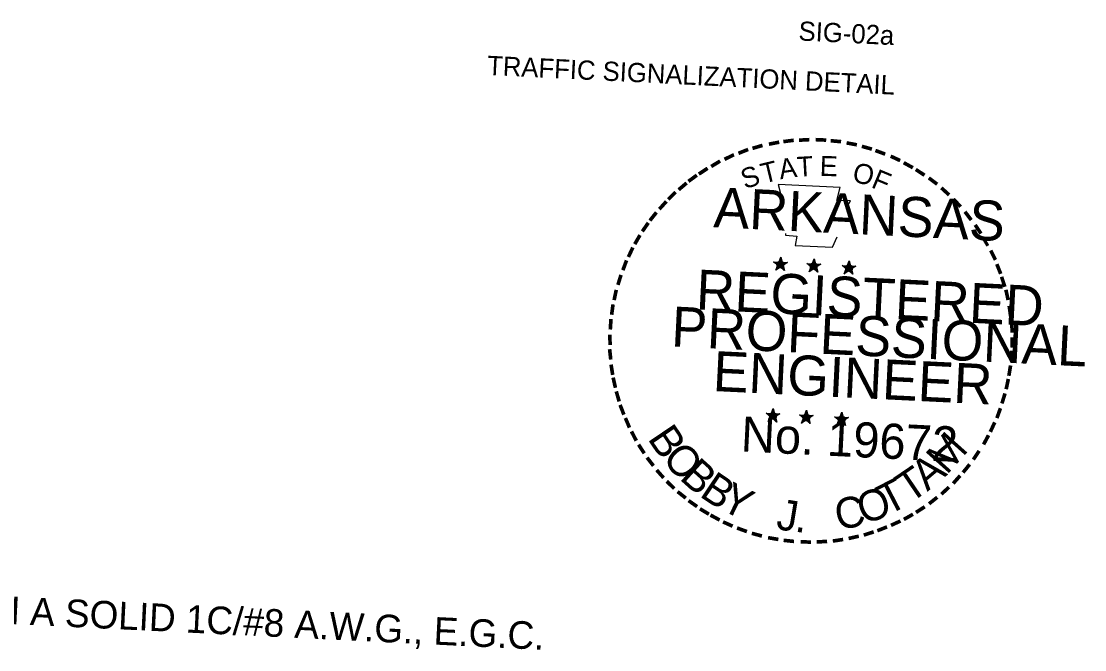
# Model space of a CAD drawing. Extents: x 661018 to 663325, y 642537 to 643074.
# Drawn here: x 662163.6 to 662293.4, y 642856.9 to 642933.6 of the extents above; entities that cross this region are included whole.
import ezdxf

# ---------------------------------------------------------------- set-up
doc = ezdxf.new("R2010")
doc.units = 0
doc.layers.add('R_Dimension', color=7, linetype='Continuous')
doc.layers.add('R_No Plot', color=7, linetype='Continuous')

msp = doc.modelspace()

# ---------------------------------------------------------------- linework, layer by layer
at = {"layer": 'R_No Plot'}
for p, q in [((662256.27, 642904.81), (662256.14, 642904.2)), ((662256.23, 642903.92), (662256.27, 642904.81)), ((662256.27, 642904.81), (662256.36, 642904.19)), ((662260.35, 642904.61), (662260.22, 642904)), ((662260.3, 642903.72), (662260.35, 642904.61)), ((662260.35, 642904.61), (662260.44, 642903.99)), ((662264.65, 642904.37), (662264.52, 642903.76)), ((662264.6, 642903.48), (662264.65, 642904.37)), ((662264.65, 642904.37), (662264.74, 642903.76)), ((662255.39, 642904.23), (662256.23, 642903.92)), ((662255.39, 642904.23), (662256, 642904.09)), ((662255.39, 642904.23), (662255.96, 642903.9)), ((662255.67, 642903.22), (662256.23, 642903.92)), ((662255.67, 642903.22), (662256.01, 642903.8)), ((662255.67, 642903.22), (662256.22, 642903.72)), ((662256.72, 642903.17), (662256.22, 642903.72)), ((662257.09, 642904.15), (662256.23, 642903.92)), ((662256.72, 642903.17), (662256.23, 642903.92)), ((662257.09, 642904.15), (662256.39, 642904.06)), ((662256.72, 642903.17), (662256.42, 642903.89)), ((662257.09, 642904.15), (662256.58, 642903.92)), ((662259.47, 642904.03), (662260.3, 642903.72)), ((662259.47, 642904.03), (662260.08, 642903.89)), ((662259.47, 642904.03), (662260.03, 642903.71)), ((662259.74, 642903.02), (662260.3, 642903.72)), ((662259.74, 642903.02), (662260.08, 642903.6)), ((662259.74, 642903.02), (662260.29, 642903.53)), ((662260.79, 642902.97), (662260.29, 642903.52)), ((662261.16, 642903.95), (662260.3, 642903.72)), ((662260.79, 642902.97), (662260.3, 642903.72)), ((662261.16, 642903.95), (662260.46, 642903.86)), ((662260.79, 642902.97), (662260.49, 642903.7)), ((662261.16, 642903.95), (662260.65, 642903.72)), ((662263.77, 642903.79), (662264.6, 642903.48)), ((662263.77, 642903.79), (662264.38, 642903.65)), ((662263.77, 642903.79), (662264.33, 642903.47)), ((662264.04, 642902.78), (662264.6, 642903.48)), ((662264.04, 642902.78), (662264.38, 642903.36)), ((662264.04, 642902.78), (662264.59, 642903.29)), ((662265.09, 642902.73), (662264.59, 642903.28)), ((662265.46, 642903.71), (662264.6, 642903.48)), ((662265.09, 642902.73), (662264.6, 642903.48)), ((662265.46, 642903.71), (662264.76, 642903.63)), ((662265.09, 642902.73), (662264.79, 642903.46)), ((662265.46, 642903.71), (662264.95, 642903.49)), ((662255.37, 642886.34), (662255.24, 642885.73)), ((662255.32, 642885.45), (662255.37, 642886.34)), ((662255.37, 642886.34), (662255.46, 642885.72)), ((662254.49, 642885.76), (662255.32, 642885.45)), ((662254.49, 642885.76), (662255.1, 642885.62)), ((662254.49, 642885.76), (662255.05, 642885.44)), ((662254.76, 642884.75), (662255.32, 642885.45)), ((662254.76, 642884.75), (662255.1, 642885.33)), ((662254.76, 642884.75), (662255.31, 642885.25)), ((662255.81, 642884.7), (662255.31, 642885.25)), ((662256.18, 642885.68), (662255.32, 642885.45)), ((662255.81, 642884.7), (662255.32, 642885.45)), ((662256.18, 642885.68), (662255.48, 642885.59)), ((662255.81, 642884.7), (662255.51, 642885.43)), ((662256.18, 642885.68), (662255.67, 642885.45)), ((662258.56, 642885.56), (662259.39, 642885.25)), ((662258.56, 642885.56), (662259.17, 642885.42)), ((662258.56, 642885.56), (662259.12, 642885.24)), ((662258.83, 642884.55), (662259.39, 642885.25)), ((662258.83, 642884.55), (662259.17, 642885.13)), ((662258.83, 642884.55), (662259.38, 642885.06)), ((662259.44, 642886.14), (662259.31, 642885.53)), ((662259.88, 642884.5), (662259.38, 642885.05)), ((662259.39, 642885.25), (662259.44, 642886.14)), ((662260.25, 642885.48), (662259.39, 642885.25)), ((662259.88, 642884.5), (662259.39, 642885.25)), ((662259.44, 642886.14), (662259.53, 642885.53)), ((662260.25, 642885.48), (662259.55, 642885.4)), ((662259.88, 642884.5), (662259.58, 642885.23)), ((662260.25, 642885.48), (662259.74, 642885.26)), ((662262.86, 642885.33), (662263.7, 642885.02)), ((662262.86, 642885.33), (662263.48, 642885.19)), ((662262.86, 642885.33), (662263.43, 642885)), ((662263.14, 642884.32), (662263.7, 642885.02)), ((662263.14, 642884.32), (662263.48, 642884.9)), ((662263.75, 642885.91), (662263.62, 642885.3)), ((662263.7, 642885.02), (662263.75, 642885.91)), ((662264.56, 642885.25), (662263.7, 642885.02)), ((662264.19, 642884.27), (662263.7, 642885.02)), ((662263.75, 642885.91), (662263.84, 642885.29)), ((662264.56, 642885.25), (662263.86, 642885.16)), ((662264.19, 642884.27), (662263.89, 642884.99)), ((662264.56, 642885.25), (662264.05, 642885.02)), ((662263.14, 642884.32), (662263.69, 642884.82)), ((662264.19, 642884.27), (662263.69, 642884.82))]:
    msp.add_line(p, q, dxfattribs=at)
for points in [[(662255.95, 642913.68), (662256.51, 642911.63)], [(662264.41, 642911.02), (662264.79, 642911.69), (662263.11, 642911.72), (662263.55, 642913.31), (662255.95, 642913.68)], [(662256.87, 642907.72), (662256.86, 642907.5), (662258.23, 642907.39), (662258.04, 642906.24), (662262.6, 642906.02), (662263.15, 642907.3)], [(662256.27, 642904.81), (662256.72, 642903.17), (662255.39, 642904.23), (662257.09, 642904.15), (662255.67, 642903.22), (662256.27, 642904.81)], [(662260.35, 642904.61), (662260.79, 642902.97), (662259.47, 642904.03), (662261.16, 642903.95), (662259.74, 642903.02), (662260.35, 642904.61)], [(662264.65, 642904.37), (662265.09, 642902.73), (662263.77, 642903.79), (662265.46, 642903.71), (662264.04, 642902.78), (662264.65, 642904.37)], [(662255.37, 642886.34), (662255.81, 642884.7), (662254.49, 642885.76), (662256.18, 642885.68), (662254.76, 642884.75), (662255.37, 642886.34)], [(662259.44, 642886.14), (662259.88, 642884.5), (662258.56, 642885.56), (662260.25, 642885.48), (662258.83, 642884.55), (662259.44, 642886.14)], [(662263.75, 642885.91), (662264.19, 642884.27), (662262.86, 642885.33), (662264.56, 642885.25), (662263.14, 642884.32), (662263.75, 642885.91)]]:
    msp.add_lwpolyline(points, dxfattribs=at)
for centre, radius in [((662256.23, 642903.92), 0.421), ((662256.23, 642903.92), 0.353), ((662256.23, 642903.92), 0.283), ((662256.23, 642903.92), 0.242), ((662256.23, 642903.92), 0.182), ((662256.23, 642903.92), 0.121), ((662256.23, 642903.92), 0.0724), ((662260.3, 642903.72), 0.421), ((662260.3, 642903.72), 0.353), ((662260.3, 642903.72), 0.283), ((662260.3, 642903.72), 0.242), ((662260.3, 642903.72), 0.182), ((662260.3, 642903.72), 0.121), ((662260.3, 642903.72), 0.0724), ((662264.6, 642903.48), 0.421), ((662264.6, 642903.48), 0.353), ((662264.6, 642903.48), 0.283), ((662264.6, 642903.48), 0.242), ((662264.6, 642903.48), 0.182), ((662264.6, 642903.48), 0.121), ((662264.6, 642903.48), 0.0724), ((662255.32, 642885.45), 0.421), ((662255.32, 642885.45), 0.353), ((662255.32, 642885.45), 0.283), ((662255.32, 642885.45), 0.242), ((662255.32, 642885.45), 0.182), ((662255.32, 642885.45), 0.121), ((662255.32, 642885.45), 0.0724), ((662259.39, 642885.25), 0.421), ((662259.39, 642885.25), 0.353), ((662259.39, 642885.25), 0.283), ((662259.39, 642885.25), 0.242), ((662259.39, 642885.25), 0.182), ((662259.39, 642885.25), 0.121), ((662259.39, 642885.25), 0.0724), ((662263.7, 642885.02), 0.421), ((662263.7, 642885.02), 0.353), ((662263.7, 642885.02), 0.283), ((662263.7, 642885.02), 0.242), ((662263.7, 642885.02), 0.182), ((662263.7, 642885.02), 0.121), ((662263.7, 642885.02), 0.0724)]:
    msp.add_circle(centre, radius, dxfattribs=at)

# ---------------------------------------------------------------- texts
at = {"layer": 'R_Dimension'}
msp.add_text(' 1/2" NMC WITH A SOLID 1C/#8 A.W.G., E.G.C.', height=3.3692, rotation=357.2199, dxfattribs=at).set_placement((662129.98, 642861.62))
at = {"layer": 'R_No Plot'}
for s, height, rotation, p in [('SIG-02a', 2.345, 357.2199, (662258.41, 642931.26)), ('TRAFFIC SIGNALIZATION DETAIL', 2.3448, 357.2199, (662220.39, 642927.06)), ('-', 3.91, 16.3944, (662253.03, 642916.58)), ('-', 3.91, 10.8485, (662254.89, 642917.08)), ('-', 3.91, 7.4377, (662256.56, 642917.39)), ('-', 3.91, 3.1152, (662258.35, 642917.57)), ('-', 3.91, 357.4046, (662260.25, 642917.66)), ('-', 3.91, 354.9614, (662262.01, 642917.54)), ('-', 3.91, 349.3801, (662263.81, 642917.32)), ('-', 3.91, 26.0102, (662249.87, 642915.3)), ('-', 3.91, 21.5255, (662251.45, 642916)), ('-', 3.91, 344.4232, (662265.55, 642916.95)), ('-', 3.91, 339.5545, (662267.09, 642916.5)), ('-', 3.91, 31.2819, (662248.37, 642914.47)), ('T', 2.44, 13.6219, (662254.17, 642913.79)), ('A', 2.44, 8.4315, (662256.22, 642914.31)), ('T', 2.44, 3.2411, (662258.31, 642914.61)), ('E', 2.44, 358.0507, (662261.01, 642914.75)), ('O', 2.44, 347.6698, (662264.9, 642914.04)), ('-', 3.91, 335.0734, (662268.85, 642915.87)), ('-', 3.91, 331.3394, (662270.36, 642915.13)), ('-', 3.91, 36.169, (662245.71, 642912.71)), ('-', 3.91, 33.4501, (662246.92, 642913.57)), ('S', 2.44, 18.8123, (662251.9, 642913.09)), ('F', 2.44, 337.289, (662267.2, 642913.38)), ('-', 3.91, 326.8592, (662271.74, 642914.38)), ('-', 3.91, 40.1806, (662244.61, 642911.74)), ('-', 3.91, 323.081, (662273.26, 642913.42)), ('-', 3.91, 45.6414, (662243.46, 642910.63)), ('ARKANSAS', 4.883, 357.2183, (662248.01, 642908.48)), ('-', 3.91, 317.748, (662274.7, 642912.31)), ('-', 3.91, 47.8325, (662242.42, 642909.49)), ('-', 3.91, 312.7969, (662276.1, 642911.05)), ('-', 3.91, 51.4508, (662241.34, 642908.16)), ('-', 3.91, 307.0981, (662277.42, 642909.64)), ('-', 3.91, 55.289, (662240.49, 642906.91)), ('-', 3.91, 303.8705, (662278.63, 642908.11)), ('-', 3.91, 60.0897, (662239.65, 642905.45)), ('-', 3.42, 300.8936, (662279.75, 642906.66)), ('-', 3.91, 64.9926, (662238.95, 642903.99)), ('-', 3.91, 296.8867, (662280.46, 642905.15)), ('-', 3.91, 69.6128, (662238.34, 642902.48)), ('REGISTERED', 4.883, 357.2183, (662245.86, 642898.44)), ('-', 3.91, 291.8811, (662281.17, 642903.62)), ('-', 3.91, 72.6793, (662237.77, 642900.76)), ('-', 3.91, 287.7912, (662281.73, 642902.18)), ('-', 3.91, 78.4196, (662237.37, 642899.04)), ('-', 3.91, 282.3416, (662282.24, 642900.74)), ('-', 3.91, 82.4047, (662237.1, 642897.36)), ('PROFESSIONAL', 4.8833, 357.2183, (662242.84, 642893.93)), ('-', 3.91, 277.7677, (662282.64, 642898.9)), ('-', 3.91, 86.2806, (662236.96, 642895.66)), ('-', 3.91, 273.8145, (662282.94, 642897.01)), ('-', 3.91, 91.4142, (662236.96, 642893.89)), ('-', 3.91, 271.5484, (662283, 642895.24)), ('-', 3.91, 96.1663, (662237.05, 642892.25)), ('ENGINEER', 4.883, 357.2183, (662247.92, 642888.49)), ('-', 3.91, 267.159, (662283.01, 642893.7)), ('-', 3.91, 98.9333, (662237.29, 642890.45)), ('-', 3.91, 260.7355, (662282.88, 642892.07)), ('-', 3.91, 102.6762, (662237.62, 642888.98)), ('-', 3.91, 258.2136, (662282.63, 642890.49)), ('-', 3.91, 106.3058, (662238.07, 642887.41)), ('-', 3.91, 252.9809, (662282.28, 642888.85)), ('-', 3.91, 111.2827, (662238.62, 642885.93)), ('-', 3.91, 250.0864, (662281.76, 642887.11)), ('-', 3.91, 112.9472, (662239.29, 642884.39)), ('No. 19672', 4.29, 357.2183, (662251.35, 642881.11)), ('-', 3.91, 117.6655, (662240.09, 642882.91)), ('B', 3.76, 304.0732, (662239.95, 642882.68)), ('-', 3.91, 245.107, (662281.13, 642885.5)), ('M', 3.76, 48.2474, (662276.53, 642878.17)), ('-', 3.91, 241.838, (662280.42, 642884)), ('-', 3.91, 123.1118, (662241.01, 642881.5)), ('O', 3.76, 312.1834, (662241.68, 642880.12)), ('-', 3.91, 236.2896, (662279.37, 642882.21)), ('-', 3.91, 127.9365, (662242.07, 642880.1)), ('B', 3.76, 317.964, (662243.8, 642877.79)), ('A', 3.76, 40.1373, (662274.17, 642876.16)), ('-', 3.91, 131.4421, (662243.26, 642878.71)), ('B', 3.76, 326.0742, (662246.23, 642875.71)), ('T', 3.76, 34.2369, (662272.02, 642874.7)), ('-', 3.91, 231.0636, (662278.31, 642880.66)), ('-', 3.91, 136.1522, (662244.49, 642877.51)), ('Y', 3.76, 334.1844, (662248.71, 642874.11)), ('T', 3.76, 27.3561, (662269.32, 642873.24)), ('-', 3.91, 228.4721, (662277.2, 642879.33)), ('-', 3.91, 141.8647, (662245.8, 642876.46)), ('O', 3.76, 19.2459, (662266.38, 642872.16)), ('-', 3.91, 222.9837, (662275.96, 642878.02)), ('-', 3.91, 145.3081, (662247.12, 642875.49)), ('J', 3.76, 350.5606, (662255.61, 642871.66)), ('C', 3.76, 11.1357, (662263.27, 642871.47)), ('-', 3.91, 212.9547, (662273.23, 642875.75)), ('-', 3.91, 218.3034, (662274.63, 642876.84)), ('-', 3.91, 148.7887, (662248.49, 642874.62)), ('-', 3.91, 151.8185, (662249.74, 642873.96)), ('-', 3.91, 209.4674, (662271.88, 642874.87)), ('-', 3.91, 155.7795, (662251.23, 642873.27)), ('-', 3.91, 160.0166, (662252.88, 642872.67)), ('-', 3.91, 201.4699, (662268.92, 642873.39)), ('-', 3.91, 204.5752, (662270.48, 642874.09)), ('-', 3.91, 164.7738, (662254.6, 642872.18)), ('-', 3.91, 170.3338, (662256.47, 642871.82)), ('.', 3.76, 350.5606, (662257.9, 642871.36)), ('-', 3.91, 192.6926, (662265.7, 642872.29)), ('-', 3.91, 197.9368, (662267.38, 642872.8)), ('-', 3.91, 173.7366, (662258.29, 642871.6)), ('-', 3.91, 178.6215, (662260.24, 642871.55)), ('-', 3.91, 183.035, (662262.09, 642871.65)), ('-', 3.91, 188.5041, (662263.9, 642871.89))]:
    msp.add_text(s, height=height, rotation=rotation, dxfattribs=at).set_placement(p)

doc.saveas('drawing.dxf')
